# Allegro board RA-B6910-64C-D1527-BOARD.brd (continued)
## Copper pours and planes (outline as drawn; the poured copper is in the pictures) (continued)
Net_32 on TOP (solid shape): outline of 184 points within 177.34,149.78 180.89,153.34
Net_33 on BOTTOM (solid shape): outline of 184 points within 175.82,155.24 179.37,158.8
Net_279 on TOP (solid shape): outline of 184 points within 18.84,143.56 22.4,147.12
Net_280 on TOP (solid shape): outline of 184 points within 9.83,15.29 13.38,18.85
Net_281 on BOTTOM (solid shape): outline of 184 points within 18.84,143.56 22.4,147.12
Net_282 on BOTTOM (solid shape): outline of 184 points within 9.83,15.29 13.38,18.85
PLLAV33 on BOTTOM: 137.84,140.39 139.37,140.39 139.49,140.26 139.49,138.48 139.37,138.35 137.84,138.35 137.59,138.61 137.59,140.13
PLLAV33 on SIG1: 143.05,121.46 137.21,127.31 137.21,138.99 137.59,139.37 140.51,139.37 141.02,138.86 141.02,130.1 142.86,128.26 142.86,125.21 144.32,123.75 148.51,123.75 148.76,123.5 148.76,121.84 148.38,121.46
VPLLAV33 on SIG1: 150.54,115.62 157.15,115.62 157.27,115.75 157.27,116.89 156.64,117.53 150.67,117.53 150.41,117.27 150.41,115.75
N1731523 on BOTTOM: 126.03,123.24 127.68,123.24 128.19,123.75 128.19,127.43 128.06,127.56 126.03,127.56 125.9,127.43 125.9,123.37
N1746574 on BOTTOM: 92.5,139.75 92.38,139.62 90.85,139.62 90.6,139.88 90.6,148.01 91.23,148.64 92.38,148.64 92.5,148.51
N1746574 on SIG4: 90.34,138.23 92.25,140.13 92.25,141.91 92.12,142.04 88.44,142.04 87.3,140.89 81.33,140.89 79.04,138.61 79.04,134.8 79.29,134.54 89.71,134.54 90.34,135.18
N1767081 on TOP: 172,150.42 173.91,150.42 174.16,150.17 174.16,148.13 174.42,147.88 176.7,147.88 176.83,147.75 176.83,146.99 176.7,146.86 175.18,146.86 173.78,145.47 173.78,144.2 173.53,143.94 172,143.94 171.88,144.07 171.88,150.29
N1774644 on TOP: 171.75,140.01 173.66,140.01 173.91,139.75 173.91,137.72 174.16,137.47 176.45,137.47 176.58,137.34 176.58,136.58 176.45,136.45 174.93,136.45 173.53,135.05 173.53,133.78 173.27,133.53 171.75,133.53 171.62,133.66 171.62,139.88
N1789392 on TOP: 158.42,54.15 161.34,54.15 161.46,54.28 161.46,58.22 161.72,58.47 163.75,58.47 163.88,58.6 163.88,59.23 163.75,59.36 162.1,59.36 160.83,60.63 158.42,60.63 158.16,60.38 158.16,54.41
N12522404 on TOP: 182.42,156.39 182.42,157.53 182.8,157.91 184.07,157.91 184.2,158.04 184.2,159.69 183.56,160.33 180.01,160.33 179.88,160.2 179.88,155.5 180.13,155.25 181.28,155.25
N12565730 on TOP: 139.37,98.98 141.27,98.98 141.65,98.6 141.65,96.83 141.33,96.51 138.54,96.51 138.48,96.57 138.48,98.1
N12565730 on BOTTOM: 134.67,98.73 139.24,98.73 139.37,98.6 139.37,97.08 139.24,96.95 138.35,96.95 137.97,97.33 134.79,97.33 134.54,97.59 134.54,98.6
N13474364 on TOP: 198.54,41.26 200.9,41.26 201.21,41.58 201.21,45.01 200.96,45.26 196.9,45.26 194.1,42.47 194.1,39.8 194.23,39.68 195.75,39.68 196.01,39.93 197.21,39.93
N13478791 on TOP: 140.89,158.67 143.68,158.67 143.81,158.55 143.81,155.12 143.68,154.99 141.02,154.99 140.89,155.12 140.89,156.64 140.51,157.02 138.6,157.02 138.35,157.28 138.35,157.79 138.6,158.04 140.25,158.04
N13485295 on TOP: 160.07,64.95 162.48,64.95 162.73,65.2 162.73,67.11 163.88,68.25 165.27,68.25 165.53,68.5 165.53,69.01 165.4,69.14 163.62,69.14 162.99,69.77 160.07,69.77 159.94,69.65 159.94,65.08
N16755005 on TOP: 30.91,32.18 30.91,30.4 30.78,30.28 28.88,30.28 28.75,30.4 28.75,33.33 28.88,33.45 29.51,33.45 29.64,33.33 29.64,32.56 29.89,32.31 30.78,32.31
N16755005 on BOTTOM: 30.78,34.34 30.78,30.15 30.53,29.9 29.13,29.9 28.88,30.15 28.88,32.82 28.37,33.33 27.22,33.33 26.97,33.58 26.97,34.6 27.1,34.72 30.4,34.72
N17832270 on TOP: 60.12,146.48 62.91,146.48 63.29,146.1 63.29,144.07 63.17,143.94 60.37,143.94 59.99,144.32 59.99,146.36
N17832270 on BOTTOM: 59.1,146.48 60.88,146.48 61.01,146.36 61.01,144.58 60.88,144.45 59.1,144.45 58.97,144.58 58.97,146.36
N18052836 on TOP (solid shape): 182.91,11.23 182.91,9.7 183.79,8.81 187.12,8.81 187.24,8.69 187.24,4.12 187.12,3.99 184.2,3.99 183.94,4.24 183.94,6.78 182.19,8.54 182.19,11.23 182.4,11.44 182.7,11.44

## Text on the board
Ref Des/Silkscreen Bottom: B | A | RE.100D0801031,8624
User.Comments: PARTITION_2
Ref Des/Silkscreen Top: VDD1.8V | P3V3_STBY | VDD_BMC_2.5V | P1V05_VCCSCSUS | VCC_BMC_DDR | P3V3_AUX | P0V6_M_ABC_VTT | PVDDQ_CPU_ABC | P1V3_VCCKRHV | P1V7_VCCSCFUSESUS | P1V5_VRM | PVCCCIN | P1V05_VCCCIOIN | VCC_1V15_AUX | P5V_AUX | C | F | E | J | D | I | G | H | A | 1801-02FEAZ-DH22H03-04AEBG-02150118 | V1.00 | S/N1
SCREW: GND2 | GND1
User.5: BACKDRILL_B:NULL:T-S4@BOTTOM-SIG4@ | BACKDRILL_B:NULL:B-S1@TOP-SIG1@
User.17: FIGURE | SIZE | 8.0 | 8.1 | 9.0 | 16.0 | 20.0 | 39.37 | 40.0 | 63.0 | 137.8 | 169.29 | 43.31 | 50.0 | 62.99 | 129.92 | DRILL CHART: TOP to BOTTOM | ALL UNITS ARE IN MILS | PLATED | NON-PLATED | QTY | 6275 | 4 | 71 | 250 | 90 | 12 | 2 | 3 | 9
